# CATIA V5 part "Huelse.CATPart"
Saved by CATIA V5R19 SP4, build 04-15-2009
Part number: Hülse
Bounding box of the stored display mesh (mm): x -30 to 30, y -40 to 40, z -30 to 30
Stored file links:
  C:\Users\schneidp\Desktop\Manikan\V5R19\Huelse.CATPart
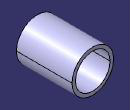
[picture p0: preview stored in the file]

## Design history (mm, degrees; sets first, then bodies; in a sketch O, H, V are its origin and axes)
Body1 (main body)
  Sketch1 on zx-plane, origin (0, 0, 0), H (-1, 0, 0), V (0, 0, 1)
    circle A1 centre (0, 0) radius 30
    circle A2 centre (0, 0) radius 25
    radius A2 = 25
    radius A1 = 30
  Pad1: profile Sketch1, direction (0, 1, 0), length 40, mirrored extent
